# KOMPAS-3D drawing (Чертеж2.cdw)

Views: Вид 1
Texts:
  илья
  Установка привода
  1-электродвигатель 2-подмуфта 3 -подмуфта
  4 - редуктор 5 -полумуфта
  Натяжная станция
  1-рама 2-тележка 3 -лебёдка ЛР 15,00,000
  4-плита анкерная 5-стяжка
  Тележка 637.66.01.000
  1-барабан 2-каток 3-рама 4-кожух
  Конвейер Л1000КУ
  1-приводная станция 2-натяжная станция 3-канат
  4-ограждение 5-установка барабанов 6-утановка привода
  7-стойка 8-роликоопора  9-переходной мостик
  10-скребок 11-роликоопора  12-ролик 13-трёхроликовая гирлянда
  Разраб.
  Пров.
  Галинов И.С.
  Маллер В.Т.
Dimensions and other numbers on the sheet: 5-лоток 6-блок; 5; 4; 2; 3; 1; 1050; 2150; 1410; 2135; 3700; 1000; 904; 2325; 1800; 3500; 1022; 1300; 2000; 6; 10; 7; 8; 9; 11; 12; 13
